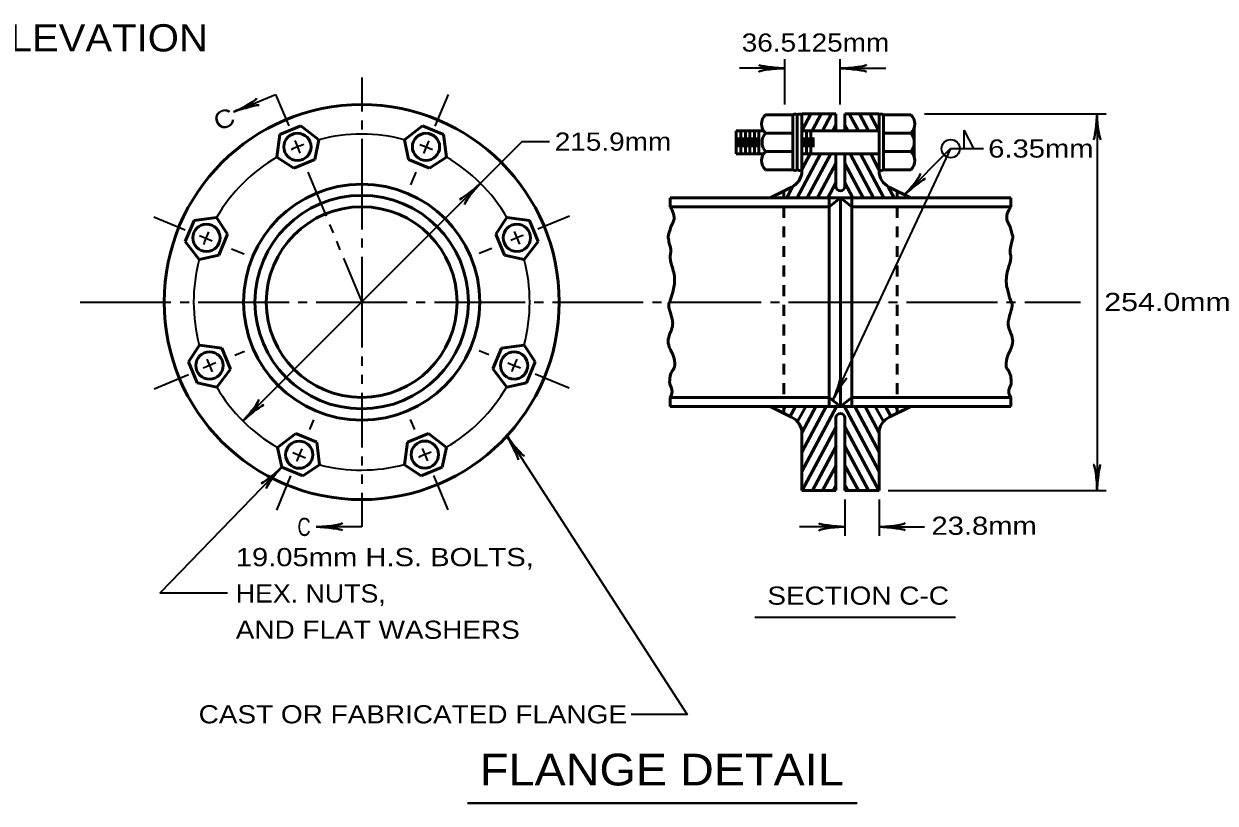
# Model space of a CAD drawing. Extents: x -35 to 821, y -13 to 531.
# Drawn here: x 298.4 to 455.8, y 249.6 to 352.6 of the extents above; entities that cross this region are included whole.
import ezdxf

# ---------------------------------------------------------------- set-up
doc = ezdxf.new("R2010")
doc.units = 0
doc.header["$LTSCALE"] = 0.96
doc.linetypes.add('SHORT_DASHED', pattern=[2.7, 1.5, -1.2])
doc.layers.add('1', color=7, linetype='Continuous', lineweight=53)

msp = doc.modelspace()

# ---------------------------------------------------------------- linework, layer by layer
at = {"layer": '1', "lineweight": 35}
for p, q in [((398.9783, 341.8992), (398.9783, 347.8992)), ((406.3125, 341.8992), (406.3125, 347.8992)), ((398.9783, 346.6992), (392.9783, 346.6992)), ((406.3125, 346.6992), (412.3125, 346.6992)), ((326.1673, 340.942), (331.7104, 343.2383)), ((331.7104, 343.2383), (333.4327, 339.0808)), ((354.4801, 343.2225), (352.7522, 339.0674)), ((417.4296, 340.6992), (441.4296, 340.6992)), ((440.2296, 340.6992), (440.2292, 290.8992)), ((343.0763, 339.7992), (343.0763, 338.5992)), ((364.2895, 337.0124), (327.3785, 300.1014)), ((334.2364, 337.1406), (334.5806, 336.3093)), ((343.0763, 337.3992), (343.0763, 325.3992)), ((364.2895, 337.0124), (367.8895, 337.0124)), ((334.5807, 336.3093), (334.9252, 335.4777)), ((350.7497, 336.6459), (351.5809, 336.3015)), ((351.581, 336.3016), (352.4126, 335.9571)), ((420.8861, 336.0817), (405.3042, 302.8195)), ((414.8054, 330.001), (420.8861, 336.0817)), ((420.8861, 336.0817), (425.2492, 336.0817)), ((335.9584, 332.9832), (338.3693, 327.1628)), ((350.2181, 332.9733), (349.5269, 331.3114)), ((315.6005, 327.0762), (319.7635, 325.3676)), ((338.8285, 326.0541), (339.2878, 324.9455)), ((370.5252, 327.1413), (366.3663, 325.4228)), ((321.6657, 324.5931), (322.4969, 324.2486)), ((322.497, 324.2487), (323.3286, 323.9043)), ((363.2422, 325.1261), (363.5864, 324.2948)), ((363.5865, 324.2948), (363.931, 323.4632)), ((325.8692, 322.8616), (327.5345, 322.1781)), ((339.747, 323.8368), (340.2062, 322.7281)), ((343.0763, 324.1992), (343.0763, 322.9992)), ((360.2665, 322.9023), (358.6029, 322.2149)), ((340.6655, 321.6195), (343.0763, 315.7992)), ((305.8763, 315.7992), (317.8763, 315.7992)), ((319.0763, 315.7992), (320.2763, 315.7992)), ((321.4763, 315.7992), (333.4763, 315.7992)), ((334.6763, 315.7992), (335.8763, 315.7992)), ((337.0763, 315.7992), (349.0763, 315.7992)), ((350.2763, 315.7992), (351.4763, 315.7992)), ((352.6763, 315.7992), (364.6763, 315.7992)), ((365.8763, 315.7992), (367.0763, 315.7992)), ((368.2763, 315.7992), (380.2763, 315.7992)), ((381.4763, 315.7992), (382.6763, 315.7992)), ((383.8763, 315.7992), (395.8763, 315.7992)), ((397.0763, 315.7992), (398.2763, 315.7992)), ((399.4763, 315.7992), (411.4763, 315.7992)), ((412.6763, 315.7992), (413.8763, 315.7992)), ((415.0763, 315.7992), (427.0763, 315.7992)), ((428.2763, 315.7992), (429.4763, 315.7992)), ((430.6763, 315.7992), (438.0631, 315.7992)), ((326.2995, 308.7941), (327.5735, 309.3261)), ((343.0763, 308.5992), (343.0763, 307.3992)), ((359.8915, 308.8179), (358.5921, 309.3574)), ((322.6253, 308.2577), (322.9695, 307.4264)), ((322.9696, 307.4264), (323.3141, 306.5948)), ((362.3899, 307.7807), (363.2211, 307.4363)), ((363.2212, 307.4363), (364.0528, 307.0919)), ((315.6694, 304.3557), (320.2092, 306.2513)), ((343.0763, 306.1992), (343.0763, 304.9992)), ((370.5062, 304.411), (365.987, 306.2873)), ((343.0763, 303.7992), (343.0763, 296.5992)), ((336.2158, 298.9537), (336.7397, 300.2401)), ((349.5033, 300.2772), (350.0457, 298.9675)), ((333.984, 295.9218), (334.8152, 295.5774)), ((351.0786, 296.4727), (351.4228, 295.6414)), ((334.8153, 295.5774), (335.6469, 295.233)), ((343.0763, 295.3992), (343.0763, 294.1992)), ((351.4229, 295.6414), (351.7674, 294.8098)), ((331.874, 288.2928), (333.7264, 292.8412)), ((343.0763, 292.9992), (343.0763, 291.7992)), ((352.5704, 292.8695), (354.4383, 288.3585)), ((343.0763, 290.5992), (343.0763, 286.0992)), ((406.9292, 289.6992), (406.9292, 284.8992)), ((411.4292, 289.6992), (411.4292, 284.8992)), ((412.6292, 290.8992), (441.4292, 290.8992)), ((343.0763, 286.0992), (337.0763, 286.0992)), ((406.9292, 286.0992), (400.9292, 286.0992)), ((411.4292, 286.0992), (417.4292, 286.0992)), ((395.0103, 274.1448), (421.5211, 274.1448))]:
    msp.add_line(p, q, dxfattribs=at)
at = {"layer": '1'}
for p, q in [((400.0296, 340.5492), (396.4296, 340.5492)), ((400.0296, 333.2973), (400.0296, 340.5492)), ((400.6296, 333.2973), (400.6296, 340.5492)), ((401.2296, 333.1473), (401.2296, 340.6992)), ((401.2296, 340.6992), (405.7296, 340.6992)), ((401.2296, 338.4492), (402.4296, 340.6992)), ((402.5896, 338.4492), (403.7896, 340.6992)), ((403.9496, 338.4492), (405.1496, 340.6992)), ((405.7296, 340.6992), (405.7296, 338.4492)), ((411.4296, 340.6992), (406.9296, 340.6992)), ((406.9296, 340.6992), (406.9296, 338.4492)), ((408.6966, 338.4492), (407.4966, 340.6992)), ((410.0566, 338.4492), (408.8566, 340.6992)), ((411.4166, 338.4492), (410.2166, 340.6992)), ((411.4296, 333.1473), (411.4296, 340.6992)), ((412.0296, 333.2973), (412.0296, 340.5492)), ((415.6296, 340.5492), (412.0296, 340.5492)), ((335.048, 339.1006), (332.2765, 337.9524)), ((351.1046, 339.1006), (353.8761, 337.9524)), ((396.1662, 338.4492), (392.5662, 338.4492)), ((392.5662, 338.4492), (392.5662, 335.3973)), ((393.1662, 338.4492), (393.1662, 335.3973)), ((393.7662, 338.4492), (393.7662, 335.3973)), ((394.3662, 338.4492), (394.3662, 335.3973)), ((394.9662, 338.4492), (394.9662, 335.3973)), ((395.5662, 338.4492), (395.5662, 335.3973)), ((401.2296, 338.4492), (411.4296, 338.4492)), ((401.8296, 335.3973), (401.8296, 338.4492)), ((402.4296, 335.3973), (402.4296, 338.4492)), ((405.3096, 338.4492), (405.7296, 339.2368)), ((407.3366, 338.4492), (406.9166, 339.2368)), ((416.0836, 338.8318), (416.0836, 335.0147)), ((392.8662, 337.5492), (392.8662, 336.2973)), ((393.4662, 337.5492), (393.4662, 336.2973)), ((394.0662, 337.5492), (394.0662, 336.2973)), ((394.6662, 337.5492), (394.6662, 336.2973)), ((395.2662, 337.5492), (395.2662, 336.2973)), ((400.0296, 338.1492), (396.4296, 338.1492)), ((401.5296, 336.2973), (401.5296, 337.5492)), ((402.1296, 336.2973), (402.1296, 337.5492)), ((402.7296, 336.2973), (402.7296, 337.5492)), ((415.6296, 338.1492), (412.0296, 338.1492)), ((396.1662, 335.3973), (392.5662, 335.3973)), ((400.0296, 335.6973), (396.4296, 335.6973)), ((400.5897, 329.5992), (403.6819, 335.3973)), ((401.2296, 335.3973), (411.4296, 335.3973)), ((401.2296, 333.3493), (402.3219, 335.3973)), ((401.9497, 329.5992), (405.0419, 335.3973)), ((405.7296, 335.3973), (405.7296, 331.0992)), ((406.9296, 335.3973), (406.9296, 331.0992)), ((410.6965, 329.5992), (407.6043, 335.3973)), ((412.0565, 329.5992), (408.9643, 335.3973)), ((411.4166, 333.3493), (410.3243, 335.3973)), ((415.6296, 335.6973), (412.0296, 335.6973)), ((336.885, 334.666), (334.1135, 333.5179)), ((349.2676, 334.666), (352.0391, 333.5179)), ((403.3096, 329.5992), (405.7296, 334.1368)), ((409.3366, 329.5992), (406.9166, 334.1368)), ((400.0296, 333.2973), (396.4296, 333.2973)), ((415.6296, 333.2973), (412.0296, 333.2973)), ((397.03, 329.5992), (399.8817, 330.9902)), ((399.2295, 329.5992), (400.0029, 331.0493)), ((404.6696, 329.5992), (405.7296, 331.5868)), ((407.9766, 329.5992), (406.9166, 331.5868)), ((413.4167, 329.5992), (412.6433, 331.0493)), ((415.6292, 329.5992), (412.7775, 330.9902)), ((383.8296, 329.5992), (383.8296, 328.3992)), ((383.8296, 329.5992), (398.8296, 329.5992)), ((397.0296, 329.5992), (398.8296, 330.4771)), ((404.8296, 329.5992), (404.8296, 301.9992)), ((406.3296, 329.5992), (406.3296, 301.9992)), ((407.8296, 329.5992), (407.8296, 301.9992)), ((413.8296, 329.5992), (428.8296, 329.5992)), ((428.8296, 329.5992), (428.8296, 328.3992)), ((383.8296, 328.3992), (404.8296, 328.3992)), ((407.8296, 328.3992), (428.8296, 328.3992)), ((320.9228, 326.5989), (319.7749, 323.8272)), ((365.2298, 326.5989), (366.3777, 323.8272)), ((325.3575, 324.7622), (324.2096, 321.9905)), ((360.7951, 324.7622), (361.943, 321.9905)), ((324.6129, 309.7305), (325.7608, 306.9588)), ((361.5691, 309.7325), (360.4212, 306.9608)), ((320.1782, 307.8938), (321.3261, 305.1221)), ((366.0038, 307.8958), (364.8559, 305.1241)), ((383.8296, 303.1992), (404.8296, 303.1992)), ((383.8296, 303.1992), (383.8296, 301.9992)), ((407.8296, 303.1992), (428.8296, 303.1992)), ((428.8296, 303.1992), (428.8296, 301.9992)), ((383.8296, 301.9992), (406.3296, 301.9992)), ((397.0292, 301.9992), (398.8292, 301.1213)), ((397.0296, 301.9992), (399.8813, 300.6082)), ((399.0176, 301.9992), (398.8423, 301.6705)), ((400.3775, 301.9992), (399.6891, 300.7083)), ((401.7374, 301.9992), (400.6729, 300.0031)), ((403.0974, 301.9992), (401.2413, 298.519)), ((405.8173, 301.9992), (401.2423, 293.4207)), ((404.4573, 301.9992), (401.2423, 295.9708)), ((406.3296, 301.9992), (428.8296, 301.9992)), ((406.8542, 301.9992), (411.4292, 293.4207)), ((408.2142, 301.9992), (411.4292, 295.9708)), ((409.5741, 301.9992), (411.4302, 298.519)), ((410.9341, 301.9992), (411.9986, 300.0031)), ((412.294, 301.9992), (412.9824, 300.7083)), ((415.6288, 301.9992), (412.7771, 300.6082)), ((413.6539, 301.9992), (413.8292, 301.6705)), ((405.7423, 299.3082), (401.2573, 290.8992)), ((405.7292, 290.8992), (405.7292, 300.4992)), ((406.9292, 290.8992), (406.9292, 300.4992)), ((406.9292, 299.3082), (411.4142, 290.8992)), ((334.3573, 298.4248), (337.1288, 297.2766)), ((351.89, 298.4327), (349.1185, 297.2845)), ((401.2292, 298.4511), (401.2292, 290.8992)), ((411.4292, 298.4511), (411.4292, 290.8992)), ((405.7423, 296.7584), (402.6174, 290.8992)), ((406.9292, 296.7584), (410.0541, 290.8992)), ((332.5203, 293.9902), (335.2918, 292.8421)), ((353.727, 293.9981), (350.9555, 292.85)), ((405.7423, 294.2084), (403.9774, 290.8992)), ((406.9292, 294.2084), (408.6941, 290.8992)), ((405.7423, 291.6582), (405.3375, 290.8992)), ((406.9292, 291.6582), (407.334, 290.8992)), ((401.2292, 290.8992), (405.7292, 290.8992)), ((411.4292, 290.8992), (406.9292, 290.8992))]:
    msp.add_line(p, q, dxfattribs=at)
at = {"layer": '1', "linetype": 'SHORT_DASHED'}
for p, q in [((398.8296, 328.3992), (398.8296, 303.1992)), ((413.8296, 328.3992), (413.8296, 303.1992))]:
    msp.add_line(p, q, dxfattribs=at)
at = {"layer": '1', "lineweight": 40}
msp.add_line((357.0699, 249.5733), (408.554, 249.5733), dxfattribs=at)
at = {"layer": '1', "lineweight": 35}
for points in [[(343.0763, 345.4992), (343.0763, 341.8992), (343.0763, 340.9992)], [(422.6861, 336.0817), (422.6861, 338.4817), (423.8861, 336.0817)], [(343.0763, 321.7992), (343.0763, 315.7992), (343.0763, 309.7992)], [(362.2781, 298.1215), (386.0625, 261.3001), (378.6803, 261.3001)], [(332.5203, 293.9902), (316.4456, 277.3538), (325.3658, 277.3538)]]:
    msp.add_lwpolyline(points, dxfattribs=at)
at = {"layer": '1'}
for points in [[(335.048, 339.1006), (337.4303, 337.2692), (336.885, 334.666)], [(351.1046, 339.1006), (348.7223, 337.2692), (349.2676, 334.666)], [(334.1135, 333.5179), (331.8869, 334.9731), (332.2765, 337.9524)], [(352.0391, 333.5179), (354.2657, 334.9731), (353.8761, 337.9524)], [(398.8296, 330.477), (398.8296, 329.5992), (397.0296, 329.5992)], [(398.8296, 329.5992), (406.3296, 329.5992), (413.8296, 329.5992)], [(320.9228, 326.5989), (323.9023, 326.9884), (325.3575, 324.7622)], [(365.2298, 326.5989), (362.2503, 326.9884), (360.7951, 324.7622)], [(324.2096, 321.9905), (321.6062, 321.4451), (319.7749, 323.8272)], [(361.943, 321.9905), (364.5464, 321.4451), (366.3777, 323.8272)], [(324.6129, 309.7305), (321.6334, 310.12), (320.1782, 307.8938)], [(361.5691, 309.7325), (364.5486, 310.122), (366.0038, 307.8958)], [(321.3261, 305.1221), (323.9295, 304.5767), (325.7608, 306.9588)], [(364.8559, 305.1241), (362.2525, 304.5787), (360.4212, 306.9608)], [(398.8292, 301.1214), (398.8292, 301.9992), (397.0292, 301.9992)], [(334.3573, 298.4248), (331.975, 296.5934), (332.5203, 293.9902)], [(351.89, 298.4327), (354.2723, 296.6013), (353.727, 293.9981)], [(335.2918, 292.8421), (337.5184, 294.2973), (337.1288, 297.2766)], [(350.9555, 292.85), (348.7289, 294.3052), (349.1185, 297.2845)]]:
    msp.add_lwpolyline(points, dxfattribs=at)
for points in [[(404.8296, 329.5992), (406.3296, 329.5992), (404.8296, 328.3992)], [(406.3296, 329.5992), (407.8296, 329.5992), (407.8296, 328.3992)], [(413.8296, 330.4772), (415.6296, 329.5992), (413.8296, 329.5992)], [(404.8296, 303.1992), (406.3296, 301.9992), (404.8296, 301.9992)], [(406.3296, 301.9992), (407.8296, 303.1992), (407.8296, 301.9992)], [(413.8292, 301.1212), (415.6292, 301.9992), (413.8292, 301.9992)]]:
    msp.add_lwpolyline(points, close=True, dxfattribs=at)
for centre, radius in [((334.5808, 336.3093), 1.8), ((351.5718, 336.3093), 1.8), ((343.0763, 315.7992), 15.6), ((343.0763, 315.7992), 14.1), ((343.0763, 315.7992), 12.6), ((322.5662, 324.2948), 1.8), ((363.5864, 324.2948), 1.8), ((322.9695, 307.4264), 1.8), ((363.2125, 307.4284), 1.8), ((334.8245, 295.6335), 1.8), ((351.4228, 295.6414), 1.8)]:
    msp.add_circle(centre, radius, dxfattribs=at)
at = {"layer": '1', "lineweight": 35}
msp.add_circle((420.8861, 336.0817), 1.2, dxfattribs=at)
at = {"layer": '1'}
for centre, radius, start, end in [((343.0763, 315.7992), 26.1, 90, 180), ((343.0763, 315.7992), 26.1, 0, 90), ((397.4937, 339.3492), 1.6038, 131.56497, 228.43504), ((400.3296, 340.1705), 0.4831, 51.61539, 128.38461), ((400.9296, 340.1705), 0.4831, 51.61539, 128.38461), ((411.7296, 340.1705), 0.4831, 51.61539, 128.38461), ((414.5655, 339.3492), 1.6038, 311.56496, 48.43503), ((397.8654, 336.9232), 1.888, 139.50867, 220.49133), ((414.1938, 336.9232), 1.888, 319.50867, 40.49133), ((397.4937, 334.4973), 1.6038, 131.56497, 228.43504), ((414.5655, 334.4973), 1.6038, 311.56496, 48.43503), ((398.8296, 333.1473), 2.4, 296.00001, 0), ((400.3296, 333.676), 0.4831, 231.61539, 308.38461), ((400.9296, 333.676), 0.4831, 231.61539, 308.38461), ((411.7296, 333.676), 0.4831, 231.61539, 308.38461), ((413.8296, 333.1473), 2.4, 180, 243.99999), ((406.3296, 331.1237), 0.6005, 182.33434, 357.66566), ((343.0763, 315.7992), 26.1, 180, 270), ((343.0763, 315.7992), 26.1, 270, 0), ((406.3292, 300.4747), 0.6005, 2.33434, 177.66566), ((398.8292, 298.4511), 2.4, 0, 63.99999), ((413.8292, 298.4511), 2.4, 116.00001, 180)]:
    msp.add_arc(centre, radius, start, end, dxfattribs=at)
at = {"layer": '1', "lineweight": 35}
for centre, start, end in [((343.0763, 315.7992), 75.26634, 104.73353), ((372.0911, 327.806), 155.1768, 159.82354), ((343.0763, 315.7992), 110.1768, 114.82354), ((343.0763, 315.7992), 120.26672, 149.73381), ((343.0763, 315.7992), 30.26619, 59.73328), ((343.0071, 315.7532), 155.1768, 159.82354), ((372.0821, 303.7847), 110.1768, 114.82354), ((343.0763, 315.7992), 165.2667, 194.81552), ((343.0763, 315.7992), 345.21367, 14.7333), ((331.4652, 286.9163), 110.1768, 114.82354), ((383.7313, 298.9408), 155.1768, 159.82354), ((343.0763, 315.7992), 210.38278, 240.00977), ((343.0763, 315.7992), 300.22489, 329.68554), ((355.3254, 287.0819), 155.1768, 159.82354), ((359.9185, 275.1313), 110.1768, 114.82354), ((343.0763, 315.7992), 255.5274, 284.67633)]:
    msp.add_arc(centre, 22.2, start, end, dxfattribs=at)
at = {"layer": '1', "lineweight": 40}
for centre, major_axis, ratio, start_param, end_param in [((397.6689, 346.3676), (2.1428, 0.1874), 0.122415, 0.89635335, 3.14159265), ((397.6337, 346.9531), (2.1077, -0.2108), 0.07063, 3.14071475, 5.41810995), ((407.6571, 346.4453), (-2.1077, 0.2108), 0.07063, 3.14071475, 5.41810995), ((407.6219, 347.0308), (-2.1428, -0.1874), 0.122415, 0.89635335, 3.14159265), ((327.2501, 341.7495), (-1.908, -0.9932), 0.122415, 0.89635335, 3.14159265), ((327.2501, 341.7495), (-1.908, -0.9932), 0.122415, 0.89635335, 3.14159265), ((327.5067, 341.222), (-2.0279, -0.6119), 0.07063, 3.14071475, 5.41810995), ((327.5067, 341.222), (-2.0279, -0.6119), 0.07063, 3.14071475, 5.41810995), ((439.9757, 339.3546), (-0.2108, -2.1077), 0.07063, 6.28230741, 8.55970261), ((439.9757, 339.3546), (-0.2108, -2.1077), 0.07063, 6.28230741, 8.55970261), ((440.5611, 339.3898), (-0.1874, 2.1428), 0.122415, 0.89635335, 3.14159265), ((440.5611, 339.3898), (-0.1874, 2.1428), 0.122415, 0.89635335, 3.14159265), ((415.4969, 331.1614), (-1.3827, -1.6477), 0.122415, 0.89635335, 3.14159265), ((415.9357, 330.7722), (-1.6394, -1.3414), 0.07063, 3.14071475, 5.41810995), ((357.6438, 330.7258), (1.6394, 1.3414), 0.07063, 3.14071475, 5.41810995), ((357.6438, 330.7258), (1.6394, 1.3414), 0.07063, 3.14071475, 5.41810995), ((358.0826, 330.3366), (1.3827, 1.6477), 0.122415, 0.89635335, 3.14159265), ((358.0826, 330.3366), (1.3827, 1.6477), 0.122415, 0.89635335, 3.14159265), ((405.5594, 304.1459), (-0.7393, -2.02), 0.122415, 0.89635335, 3.14159265), ((406.1045, 303.9294), (1.085, 1.8193), 0.07063, 6.28230741, 8.55970261), ((328.07, 301.2618), (-1.3827, -1.6477), 0.122415, 0.89635335, 3.14159265), ((328.5088, 300.8726), (-1.6394, -1.3414), 0.07063, 3.14071475, 5.41810995), ((362.7944, 296.8543), (0.9666, -1.8849), 0.07063, 6.28230741, 8.55970261), ((363.2671, 297.2015), (-1.3201, 1.6983), 0.122415, 0.89635335, 3.14159265), ((439.8977, 292.2086), (0.1874, -2.1428), 0.122415, 0.89635335, 3.14159265), ((440.4831, 292.2438), (0.2108, 2.1077), 0.07063, 6.28230741, 8.55970261), ((331.4034, 293.1997), (-1.6162, -1.3693), 0.07063, 6.28230741, 8.55970261), ((331.8489, 292.8181), (1.3542, 1.6712), 0.122415, 0.89635335, 3.14159265), ((338.3857, 286.4308), (-2.1428, -0.1874), 0.122415, 0.89635335, 3.14159265), ((405.5846, 286.3531), (2.1077, -0.2108), 0.07063, 3.14071475, 5.41810995), ((412.7386, 286.4308), (-2.1428, -0.1874), 0.122415, 0.89635335, 3.14159265), ((412.7386, 286.4308), (-2.1428, -0.1874), 0.122415, 0.89635335, 3.14159265), ((412.7386, 286.4308), (-2.1428, -0.1874), 0.122415, 0.89635335, 3.14159265), ((338.4209, 285.8453), (-2.1077, 0.2108), 0.07063, 3.14071475, 5.41810995), ((405.6198, 285.7676), (2.1428, 0.1874), 0.122415, 0.89635335, 3.14159265), ((412.7738, 285.8453), (-2.1077, 0.2108), 0.07063, 3.14071475, 5.41810995), ((412.7738, 285.8453), (-2.1077, 0.2108), 0.07063, 3.14071475, 5.41810995), ((412.7738, 285.8453), (-2.1077, 0.2108), 0.07063, 3.14071475, 5.41810995)]:
    msp.add_ellipse(centre, major_axis=major_axis, ratio=ratio, start_param=start_param, end_param=end_param, dxfattribs=at)
at = {"layer": '1'}
for points in [[(383.8296, 328.3992), (384.2899, 327.4536), (384.2899, 326.5512), (383.9619, 325.854), (383.6749, 324.8697), (383.5519, 324.4185), (383.5929, 324.1724), (383.7569, 323.3932), (383.9209, 322.5729), (383.8389, 321.9167), (384.0029, 320.7683), (384.2489, 319.948), (384.3719, 317.9793), (384.1669, 317.118), (383.8389, 316.0107), (383.6339, 315.3955), (383.7569, 314.7802), (384.0439, 313.7139), (384.1669, 313.0166), (384.0029, 312.1553), (383.6339, 311.13), (383.6339, 310.1046), (384.0439, 309.1613), (384.4129, 308.054), (384.3309, 307.0286), (384.0849, 306.6595), (383.7979, 305.7572), (383.8389, 304.8138), (384.0029, 304.4447), (384.0029, 303.5424), (383.8296, 303.1992)], [(428.8296, 328.3992), (428.3693, 327.4536), (428.3693, 326.5512), (428.6973, 325.854), (428.9843, 324.8697), (429.1073, 324.4185), (429.0663, 324.1724), (428.9023, 323.3932), (428.7383, 322.5729), (428.8203, 321.9167), (428.6563, 320.7683), (428.4103, 319.948), (428.2873, 317.9793), (428.4923, 317.118), (428.8203, 316.0107), (429.0253, 315.3955), (428.9023, 314.7802), (428.6153, 313.7139), (428.4923, 313.0166), (428.6563, 312.1553), (429.0253, 311.13), (429.0253, 310.1046), (428.6153, 309.1613), (428.2463, 308.054), (428.3283, 307.0286), (428.5743, 306.6595), (428.8613, 305.7572), (428.8203, 304.8138), (428.6563, 304.4447), (428.6563, 303.5424), (428.8296, 303.1992)]]:
    msp.add_spline(points, degree=3, dxfattribs=at)

# ---------------------------------------------------------------- texts
for s, height, width, p in [('FRONT ELEVATION', 3.6, 1.1, (273.3279, 348.9287)), ('36.5125mm', 2.4, 1.15, (393.2856, 348.9079)), ('215.9mm', 2.4, 1.15, (368.5826, 335.8155)), ('6.35mm', 2.4, 1.2, (425.8532, 334.9)), ('254.0mm', 2.4, 1.25, (441.1765, 314.6183)), ('C', 2.4, 0.75, (334.5936, 284.8923)), ('23.8mm', 2.4, 1.2, (418.3527, 285.0415)), ('19.05mm H.S. BOLTS,', 2.4, 1.2, (326.4423, 280.8972)), ('HEX. NUTS,', 2.4, 1.1, (326.4423, 276.0972)), ('SECTION C-C', 2.4, 1.15, (396.6702, 275.8052)), ('AND FLAT WASHERS', 2.4, 1.15, (326.4423, 271.2972)), ('CAST OR FABRICATED FLANGE', 2.4, 1.15, (321.5375, 260.1229)), ('FLANGE DETAIL', 4.2, 1.1, (358.6997, 251.9167))]:
    msp.add_text(s, height=height, dxfattribs=dict(at, width=width)).set_placement(p)
at = {"layer": '1', "width": 1.15}
msp.add_text('C', height=2.4, rotation=22.502, dxfattribs=at).set_placement((324.1264, 338.3726))

doc.saveas('drawing.dxf')
